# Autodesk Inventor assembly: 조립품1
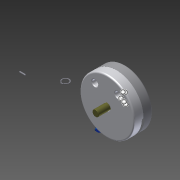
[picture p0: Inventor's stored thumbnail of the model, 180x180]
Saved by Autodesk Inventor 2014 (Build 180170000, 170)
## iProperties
Created: 2015-04
Part Number: 조립품1
Document SubType Name: Assembly
Designer: Administrator
Author: Administrator
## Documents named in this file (10)
- C:\Documents and Settings\Administrator\바탕 화면\새 폴더\조립품1.iam
- C:\Documents and Settings\Administrator\My Documents\Inventor\450405V1019\부품2.ipt
- C:\Documents and Settings\Administrator\My Documents\Inventor\450405V1019\덮개.ipt
- C:\Documents and Settings\Administrator\My Documents\Inventor\450405V1019\멈춤링.ipt
- C:\Documents and Settings\Administrator\My Documents\Inventor\450405V1019\베어링62_22.ipt
- C:\Documents and Settings\Administrator\My Documents\Inventor\450405V1019\슬라이더2.ipt
- C:\Documents and Settings\Administrator\My Documents\Inventor\450405V1019\슬라이더.ipt
- C:\Documents and Settings\Administrator\My Documents\Inventor\450405V1019\축.ipt
- C:\Documents and Settings\Administrator\My Documents\Inventor\450405V1019\평행핀.ipt
- C:\Documents and Settings\Administrator\My Documents\Inventor\450405V1019\M 10 x 35.ipt
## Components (2 placed, 1 different names)
1. M 10 x 35:1
2. M 10 x 35:2
